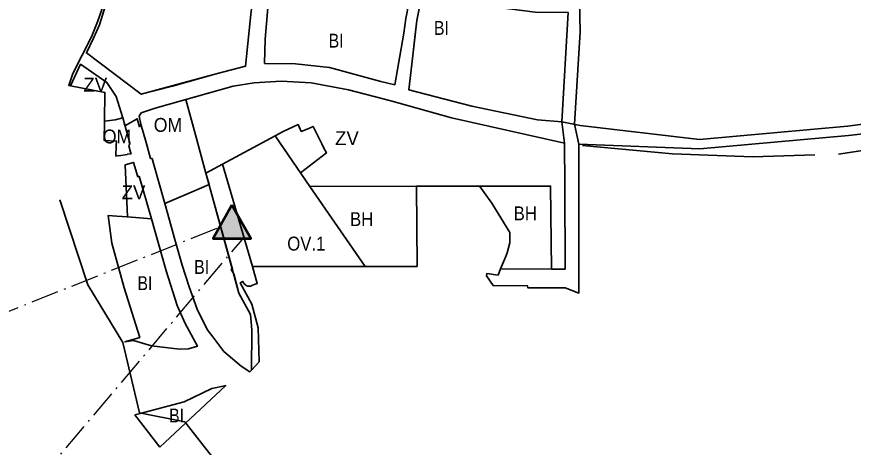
# Model space of a CAD drawing. Extents: x -650276 to -642489, y -1074311 to -1066658.
# Drawn here: x -645941 to -645218, y -1070271 to -1069899 of the extents above; entities that cross this region are included whole.
import ezdxf

# ---------------------------------------------------------------- set-up
doc = ezdxf.new("R2010")
doc.units = 0
doc.header["$LTSCALE"] = 4.8
doc.linetypes.add('DOT_DASHED', pattern=[7.7, 5, -1.2, 0.3, -1.2])
for name, color, linetype, lineweight in [('1', 7, 'Continuous', 35), ('11', 7, 'Continuous', 35), ('12', 7, 'Continuous', 35), ('15', 7, 'Continuous', 35), ('2', 7, 'Continuous', 35), ('40', 7, 'Continuous', 35), ('54', 7, 'Continuous', 35), ('55', 7, 'Continuous', 53)]:
    doc.layers.add(name, color=color, linetype=linetype, lineweight=lineweight)
doc.layers.add('62', color=7, linetype='Continuous')

msp = doc.modelspace()

# ---------------------------------------------------------------- hatches: boundary and pattern name
at = {"layer": '55'}
msp.add_hatch(color=256, dxfattribs=at).paths.add_polyline_path([(-645754.857, -1070061.969), (-645770.808, -1070090.615), (-645738.424, -1070090.615)])

# ---------------------------------------------------------------- linework, layer by layer
at = {"layer": '1'}
for points in [[(-645639.638, -1070114.895), (-645594.733, -1070114.868), (-645595.2, -1070045.403), (-645687.31, -1070045.724)], [(-645522.587, -1070116.952), (-645478.664, -1070117.114), (-645479.429, -1070045.409), (-645540.433, -1070045.752), (-645530.3, -1070060.08), (-645514.49, -1070085.4), (-645514.56, -1070090.91), (-645514.61, -1070094.35), (-645517.02, -1070103.08), (-645518.35, -1070106.87), (-645521.73, -1070114.83)]]:
    msp.add_lwpolyline(points, close=True, dxfattribs=at)
at = {"layer": '11'}
msp.add_lwpolyline([(-645639.638, -1070114.895), (-645687.31, -1070045.724), (-645717.36, -1070002.12), (-645762.868, -1070026.606), (-645757.215, -1070045.97), (-645737.075, -1070114.955)], close=True, dxfattribs=at)
at = {"layer": '12'}
for points in [[(-645794.679, -1069970.596), (-645821, -1069978), (-645833, -1069982), (-645835, -1069985), (-645833.32, -1069991.86)], [(-645777.143, -1070034.287), (-645786.238, -1070001.251), (-645794.679, -1069970.596)], [(-645833.32, -1069991.86), (-645828.9, -1070007.76), (-645825.08, -1070021.52)], [(-645825.08, -1070021.52), (-645823.76, -1070021.67), (-645822.549, -1070025.948), (-645812.76, -1070060.53), (-645783.063, -1070047.855), (-645774.423, -1070044.167), (-645777.143, -1070034.287)]]:
    msp.add_lwpolyline(points, dxfattribs=at)
msp.add_lwpolyline([(-645855.17, -1070019.44), (-645852.36, -1070019.01), (-645852.33, -1070019.2), (-645845.37, -1070018.12), (-645845.14, -1070018.08), (-645845.17, -1070017.91), (-645841.89, -1070017.42), (-645842.238, -1070016.251), (-645843.94, -1070010.6), (-645843, -1070009), (-645842.8, -1070008.59), (-645843.22, -1070007.12), (-645849.1, -1069986.42), (-645855.54, -1069988.24), (-645864.77, -1069989.26), (-645864.97, -1070006.16), (-645854.42, -1070006.47), (-645854.65, -1070010.44)], close=True, dxfattribs=at)
at = {"layer": '15'}
for points in [[(-645865.78, -1069888.76), (-645870.89, -1069903.5), (-645876.15, -1069916.47), (-645892.09, -1069947.98), (-645895.66, -1069958.42), (-645894.25, -1069958.7), (-645885.422, -1069940.184), (-645862.782, -1069955.809), (-645854.81, -1069967.927), (-645849.1, -1069986.42), (-645847.14, -1069993.34), (-645836.64, -1069987.18), (-645834.65, -1069994.21), (-645833.32, -1069991.86), (-645835, -1069985), (-645833, -1069982), (-645821, -1069978), (-645753.706, -1069959.071), (-645735.532, -1069956.306), (-645712.222, -1069954.725), (-645686.147, -1069956.306), (-645654.145, -1069962.232), (-645617.403, -1069971.714), (-645565.133, -1069986.508), (-645467.472, -1070008.38), (-645469.701, -1069990.011), (-645490.814, -1069988.074), (-645547.4, -1069976.382), (-645601.753, -1069962.317), (-645598.491, -1069932.472), (-645596.463, -1069914.335), (-645594.866, -1069902.242), (-645589.84, -1069875.892)], [(-645599.271, -1069873.685), (-645604.424, -1069900.701), (-645606.07, -1069913.163), (-645614.072, -1069957.797), (-645625.979, -1069954.92), (-645670.325, -1069943.002), (-645699.889, -1069939.714), (-645726.542, -1069939.398), (-645726.131, -1069918.457), (-645723.668, -1069891.356)], [(-645738.039, -1069894.231), (-645742.967, -1069941.862), (-645768.424, -1069948.431), (-645833, -1069966), (-645880.431, -1069930.3), (-645874.219, -1069917.496), (-645869.262, -1069905.935), (-645863.95, -1069889.468)], [(-645124.233, -1069980.695), (-645222.809, -1069993.701), (-645350.784, -1070005.227), (-645453.852, -1069992.968), (-645469.701, -1069990.011), (-645467.472, -1070008.38), (-645467.068, -1070044.959), (-645466.96, -1070117.157), (-645478.664, -1070117.114), (-645522.587, -1070116.952), (-645524.82, -1070122.48), (-645534.63, -1070121.09), (-645534.7, -1070122.95), (-645529.17, -1070131.4), (-645499.276, -1070131.652), (-645499.142, -1070133.293), (-645466.862, -1070133.219), (-645454.881, -1070137.836), (-645455.073, -1070009.111), (-645350.591, -1070013.242), (-645221.99, -1070001.66), (-645194.003, -1069998.417)], [(-645757.215, -1070045.97), (-645762.868, -1070026.606), (-645777.143, -1070034.287), (-645772.853, -1070049.868), (-645748.62, -1070137.889)], [(-645737.63, -1070147.39), (-645747.67, -1070129.14), (-645745.29, -1070127.83), (-645744.73, -1070129), (-645743.87, -1070130.15), (-645742.67, -1070131.07), (-645741.83, -1070131.53), (-645740.89, -1070131.8), (-645739.41, -1070131.93), (-645738.41, -1070131.78), (-645737.48, -1070131.45), (-645734.77, -1070130.18), (-645732.91, -1070129.5), (-645737.075, -1070114.955), (-645757.215, -1070045.97)], [(-645748.62, -1070137.889), (-645738.79, -1070156.281), (-645737.624, -1070169.544), (-645737.756, -1070204.389)], [(-645737.756, -1070204.389), (-645731.3, -1070197.24), (-645731.94, -1070167.87), (-645737.63, -1070147.39)]]:
    msp.add_lwpolyline(points, dxfattribs=at)
at = {"layer": '2'}
for points in [[(-645806, -1069959), (-645768.424, -1069948.431), (-645742.967, -1069941.862), (-645738.039, -1069894.231), (-645729.006, -1069844.136), (-645777.852, -1069832.241), (-645804.185, -1069825.84), (-645808.28, -1069865.39), (-645808.84, -1069870.75), (-645849.79, -1069868.4), (-645850.92, -1069863.41), (-645857.204, -1069862.954), (-645857.289, -1069863.338), (-645863.95, -1069889.468), (-645869.262, -1069905.935), (-645874.219, -1069917.496), (-645880.431, -1069930.3), (-645833, -1069966)], [(-645606.07, -1069913.163), (-645604.424, -1069900.701), (-645599.271, -1069873.685), (-645677.849, -1069855.3), (-645716.277, -1069847.01), (-645723.668, -1069891.356), (-645726.131, -1069918.457), (-645726.542, -1069939.398), (-645699.889, -1069939.714), (-645670.325, -1069943.002), (-645625.979, -1069954.92), (-645614.072, -1069957.797)], [(-645589.84, -1069875.892), (-645594.866, -1069902.242), (-645598.491, -1069932.472), (-645601.753, -1069962.317), (-645547.4, -1069976.382), (-645490.814, -1069988.074), (-645469.701, -1069990.011), (-645469.701, -1069990.011), (-645464.288, -1069895.362), (-645492.842, -1069895), (-645526.451, -1069890.745)], [(-645792.37, -1070186.01), (-645784.51, -1070183.77), (-645795.07, -1070164.26), (-645801.99, -1070148.51), (-645811.48, -1070118.65), (-645824.28, -1070073.67), (-645845.01, -1070072.12), (-645854.25, -1070071.4), (-645861.74, -1070070.95), (-645858.53, -1070094.64), (-645847.88, -1070133.4), (-645834.31, -1070176.15), (-645847.2, -1070180.14), (-645839.82, -1070178.94), (-645824.12, -1070183.63), (-645799.91, -1070186.32)], [(-645816.9, -1070270.96), (-645760.05, -1070217.79), (-645760.91, -1070217.98), (-645772.08, -1070220.39), (-645795.85, -1070231.81), (-645833.92, -1070241.96), (-645838.53, -1070243.19)]]:
    msp.add_lwpolyline(points, close=True, dxfattribs=at)
for points in [[(-645772.853, -1070049.868), (-645774.423, -1070044.167), (-645783.063, -1070047.855), (-645812.76, -1070060.53), (-645808.721, -1070074.795), (-645804.52, -1070089.63), (-645797.66, -1070113.88), (-645791.72, -1070132.59)], [(-645753.182, -1070121.317), (-645755.4, -1070117.6), (-645754.333, -1070117.14), (-645772.853, -1070049.868)], [(-645737.756, -1070204.389), (-645737.624, -1070169.544), (-645738.79, -1070156.281), (-645748.62, -1070137.889), (-645753.182, -1070121.317)], [(-645791.72, -1070132.59), (-645784.83, -1070151.9), (-645776.26, -1070169.44), (-645771.246, -1070175.64)], [(-645771.246, -1070175.64), (-645761.78, -1070188.29), (-645746.73, -1070201.04), (-645739.12, -1070205.9), (-645737.756, -1070204.389)]]:
    msp.add_lwpolyline(points, dxfattribs=at)
at = {"layer": '40'}
for points in [[(-645849.1, -1069986.42), (-645854.81, -1069967.927), (-645862.782, -1069955.809), (-645885.422, -1069940.184), (-645894.25, -1069958.7), (-645864.48, -1069964.53), (-645864.77, -1069989.26), (-645855.54, -1069988.24)], [(-645595.2, -1070045.403), (-645479.429, -1070045.409), (-645478.664, -1070117.114), (-645466.96, -1070117.157), (-645467.068, -1070044.959), (-645467.472, -1070008.38), (-645565.133, -1069986.508), (-645617.403, -1069971.714), (-645654.145, -1069962.232), (-645686.147, -1069956.306), (-645712.222, -1069954.725), (-645735.532, -1069956.306), (-645753.706, -1069959.071), (-645794.679, -1069970.596), (-645786.238, -1070001.251), (-645777.143, -1070034.287), (-645762.868, -1070026.606), (-645717.36, -1070002.12), (-645710.43, -1069998.39), (-645697.59, -1069992.31), (-645694.8, -1069998.22), (-645689.84, -1069996.37), (-645684.59, -1069993.87), (-645677.65, -1070007.66), (-645677.02, -1070008.93), (-645675.24, -1070012.51), (-645673.1, -1070016.78), (-645695.39, -1070034), (-645687.31, -1070045.724)], [(-645834.8, -1070036.71), (-645835.91, -1070037.31), (-645839.64, -1070024.9), (-645847.08, -1070027.09), (-645845.01, -1070072.12), (-645824.28, -1070073.67), (-645824.28, -1070073.67)]]:
    msp.add_lwpolyline(points, close=True, dxfattribs=at)
at = {"layer": '54'}
for points in [[(-645624.473, -1069340.207), (-645597.606, -1069359.137), (-645542.894, -1069403.796), (-645505.738, -1069437.197), (-645484.202, -1069466.216), (-645467.655, -1069503.794), (-645460.072, -1069535.704), (-645458, -1069561.601), (-645458, -1069658.925), (-645456, -1069668), (-645455.002, -1069859.825), (-645453.95, -1069912.05), (-645458.804, -1069992.044), (-645455.073, -1070009.111)], [(-645230.538, -1070017.864), (-644946.741, -1069974.541), (-644816.387, -1069962.572), (-644667.646, -1069930.034), (-644586.303, -1069905.244), (-644248.286, -1069794.155), (-644097.378, -1069760.147), (-643995.653, -1069721.915)], [(-645451.854, -1070010.265), (-645374.117, -1070017.569), (-645304.693, -1070020.185), (-645251.015, -1070018.538)], [(-645903.547, -1070057.381), (-645879.191, -1070130.665), (-645848.973, -1070180.543), (-645834.684, -1070241.324), (-645795.429, -1070249.201), (-645711.259, -1070356.569)]]:
    msp.add_lwpolyline(points, dxfattribs=at)
at = {"layer": '55', "linetype": 'DOT_DASHED', "lineweight": 25}
for p, q in [((-647060.176, -1070597.455), (-645765.418, -1070080.935)), ((-646590, -1071090), (-645744.292, -1070089.84))]:
    msp.add_line(p, q, dxfattribs=at)
at = {"layer": '55'}
msp.add_lwpolyline([(-645754.857, -1070061.969), (-645770.808, -1070090.615), (-645738.424, -1070090.615)], close=True, dxfattribs=at)

# ---------------------------------------------------------------- texts
at = {"layer": '62'}
for s, width, p in [('BI', 0.85, (-645580.138, -1069914.734)), ('BI', 0.85, (-645671.138, -1069925.734)), ('OM', 0.95, (-645822.28, -1069998.561)), ('OM', 0.95, (-645866.28, -1070008.561)), ('BH', 0.9, (-645511.328, -1070074.977)), ('BH', 0.9, (-645652.699, -1070079.977)), ('OV.1', 0.9, (-645706.926, -1070101.134)), ('BI', 0.85, (-645787.337, -1070121.32)), ('BI', 0.85, (-645836.337, -1070135.32)), ('BI', 0.85, (-645808.987, -1070249.726))]:
    msp.add_text(s, height=12, dxfattribs=dict(at, width=width)).set_placement(p)
for p in [(-645883.022, -1069963.776), (-645665.601, -1070009.978), (-645850.022, -1070056.776)]:
    msp.add_text('ZV', height=12, dxfattribs=at).set_placement(p)

doc.saveas('drawing.dxf')
